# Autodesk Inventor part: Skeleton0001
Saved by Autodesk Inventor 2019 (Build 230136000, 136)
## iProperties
Created: 2019-01
Part Number: Skeleton0001
Material: Generic
Document SubType Name: Modeling
Designer: ElizabethC
Density: 1 g/cm^3
Appearance: Default
_SkeletonDoc: Frame Skeleton File
_Version: 15.0.0
Author: ElizabethC
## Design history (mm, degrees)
sketch "Reference Skeleton"
